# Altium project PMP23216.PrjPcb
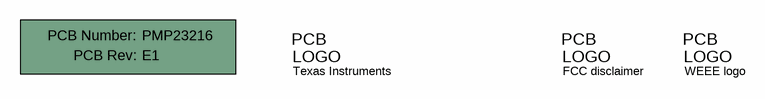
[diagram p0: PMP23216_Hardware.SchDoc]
CopyrightYear: 2022; PCB_Layout: John Gomez; PCB_Rev: E1; PRJ_Customer: Texas Instruments; PRJ_Engineer: John Gomez; PRJ_Number: PMP23216; PRJ_Title: Isolated Bias Supply for PMP22650 with Reinforced Insulation; SCH_Rev: E1; TechSupport: http://www.ti.com/support; TID: N/A
2 sheets, 29 parts. Net scope: global (net labels, ports and power ports of the same name join across sheets).
Board file: PMP23216.PcbDoc
Sheets:
  PMP23216_Hardware.SchDoc
  PMP23216_sheet1.SchDoc

## Sheet PMP23216_Hardware.SchDoc
size 431 x 279 mm; Date: Not shown in title block; ApprovedBy: Not shown in title block; CheckedBy: Not shown in title block; Author: Not shown in title block; CompanyName: Not shown in title block; Engineer: Not shown in title block; Organization: Not shown in title block; Address1: Not shown in title block; Address2: Not shown in title block; Address3: Not shown in title block; Address4: Not shown in title block; DocumentNumber: 1; Revision: Use project parameter SCH_Rev; SheetNumber: 1; SheetTotal: 2; PageSetup: Record=PageOptions¦CenterHorizontal=True¦CenterVertical=True¦PrintScale=1.00¦XCorrection=1.00¦YCorrection=1.00¦PrintKind=0¦BorderSize=5000000¦LeftOffset=0¦BottomOffset=0¦Orientation=2¦PaperLength=1000¦PaperWidth=1000¦Scale=100¦PaperSource=15¦PrintQuality=600¦MediaType=1¦DitherType=10¦PaperKind=Letter¦PrintScaleMode=1

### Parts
!PCB1  Printed Circuit Board  (value not drawn)  (mechanical)
Logo1  Texas Instruments  [TI_Symbol_Overlay_Small]  (no BOM)
Logo2  FCC disclaimer  [FCC_disclaimer]  (no BOM)
Logo3  WEEE logo  [WEEE_Minimum]  (no BOM)

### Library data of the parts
!PCB1 = CMP-0003618-2: Manufacturer: Any; PartNumber: PMP23216
Logo1 = CMP-0074838-1: Texas Instrument Corporate Signature; SymbolCreator: a0412235; Lib Reference: TI_Logo; Library Reference: Logo
Logo2 = CMP-0074847-1: FCC_disclaimer; Library Reference: Logo
Logo3 = CMP-0074769-1

## Sheet PMP23216_sheet1.SchDoc
size A2; DocumentNumber: 2; SheetNumber: 2; SheetTotal: 2; PageSetup: Record=PageOptions¦CenterHorizontal=True¦CenterVertical=True¦PrintScale=0.69¦XCorrection=1.00¦YCorrection=1.00¦PrintKind=0¦BorderSize=5000000¦LeftOffset=0¦BottomOffset=0¦Orientation=2¦PaperLength=1000¦PaperWidth=1000¦Scale=100¦PaperSource=15¦PrintQuality=600¦MediaType=1¦DitherType=10¦PaperKind=Letter¦PrintScaleMode=1
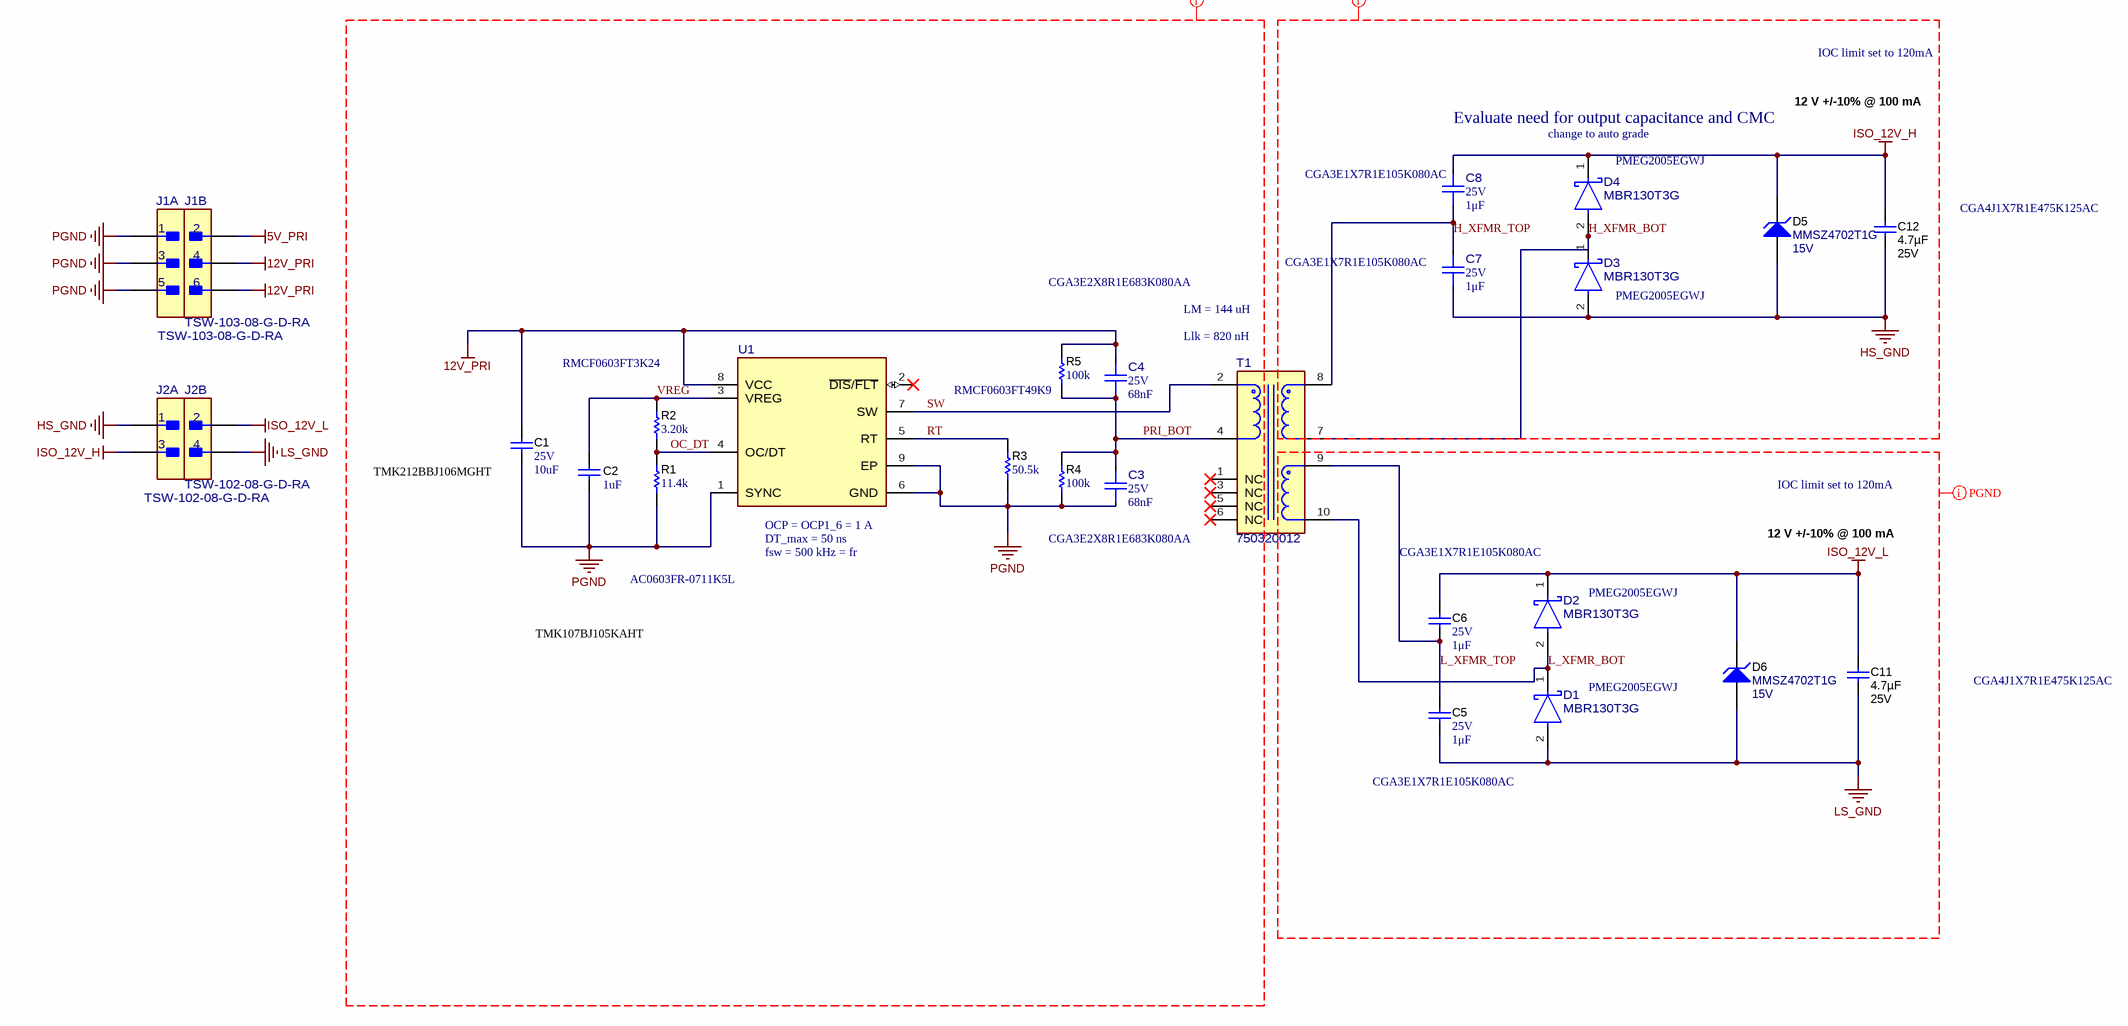
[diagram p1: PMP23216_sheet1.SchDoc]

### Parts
C1  VDC_V: 25V  ValueDisplayed: 10uF  [0805_HV]  (hidden comment: GRM219R61E106KA12D)
C2  ValueDisplayed: 1uF  [0603]  (hidden comment: GRM185R61A105KE36D)
C3  VDC_V: 25V  ValueDisplayed: 68nF  [FP-C1608X8R1E683M080AA_0603-MFG]  (hidden comment: C1608X8R1E683M080AA)
C4  VDC_V: 25V  ValueDisplayed: 68nF  [FP-C1608X8R1E683M080AA_0603-MFG]  (hidden comment: C1608X8R1E683M080AA)
C5  VDC_V: 25V  ValueDisplayed: 1μF  [0603]  (hidden comment: GRM188R61E475KE11D)
C6  VDC_V: 25V  ValueDisplayed: 1μF  [0603]  (hidden comment: GRM188R61E475KE11D)
C7  VDC_V: 25V  ValueDisplayed: 1μF  [FP-C1608X5R1E475M080AC_0603-MFG]  (hidden comment: C1608X5R1E475M080AC)
C8  VDC_V: 25V  ValueDisplayed: 1μF  [FP-C1608X5R1E475M080AC_0603-MFG]  (hidden comment: C1608X5R1E475M080AC)
C11  Cap_F: 4.7µF  VDC_V: 25V  [0805_HV]  (hidden comment: GRM21BR71E475KA73L)
C12  Cap_F: 4.7µF  VDC_V: 25V  [0805_HV]  (hidden comment: GRM21BR71E475KA73L)
D1  MBR130T3G  [FP-MBR130T3G_SOD123-MFG]
D2  MBR130T3G  [FP-MBR130T3G_SOD123-MFG]
D3  MBR130T3G  [FP-MBR130T3G_SOD123-MFG]
D4  MBR130T3G  [FP-MBR130T3G_SOD123-MFG]
D5  MMSZ4702T1G  value 15V  [SOD-123]
D6  MMSZ4702T1G  value 15V  [SOD-123]
J1  TSW-103-08-G-D-RA  [FP-TSW-103-08-G-D-RA_HDR6-MFG]  (parts A,B of 2)
J2  TSW-102-08-G-D-RA  [FP-TSW-102-08-G-D-RA_HDR4-MFG]  (parts A,B of 2)
R1  ValueDisplayed: 11.4k  [0603]  (hidden comment: RT0603DRE0711K4L)
R2  ValueDisplayed: 3.20k  [0603]  (hidden comment: RT0603BRD073K2L)
R3  ValueDisplayed: 50.5k  [0603]  (hidden comment: RT0603DRE0750K5L)
R4  ValueDisplayed: 100k  [0603]  (hidden comment: RT0603BRD073K2L)
R5  ValueDisplayed: 100k  [0603]  (hidden comment: RT0603BRD073K2L)
T1  750320012  [FP-750320012_SMT_XFRMR_20MM48_15MM32-MFG]
U1  UCC25800DGNRQ1  [DGN0008G-MFG]  (value not drawn)

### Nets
5V_PRI: J1.2
12V_PRI: C1.1 C4.2 J1.4 J1.6 R5.2 U1.8(VCC)
HS_GND: C7.1 C12.2 D3.2(ANODE) D5.2(A) J2.1
ISO_12V_H: C8.2 C12.1 D4.1(CATHODE) D5.1(K) J2.3
ISO_12V_L: C6.1 C11.1 D2.1(CATHODE) D6.1(K) J2.2
LS_GND: C5.2 C11.2 D1.2(ANODE) D6.2(A) J2.4
PGND: C1.2 C2.2 C3.1 J1.1 J1.3 J1.5 R1.1 R3.1 R4.1 U1.1(SYNC) U1.6(GND) U1.9(EP)
H_XFMR_BOT: D3.1(CATHODE) D4.2(ANODE) T1.7
H_XFMR_TOP: C7.2 C8.1 T1.8
L_XFMR_BOT: D1.1(CATHODE) D2.2(ANODE) T1.10
L_XFMR_TOP: C5.1 C6.2 T1.9
OC_DT: R1.2 R2.1 U1.4(OC/DT)
PRI_BOT: C3.2 C4.1 R4.2 R5.1 T1.4
RT: R3.2 U1.5(RT)
SW: T1.2 U1.7(SW)
VREG: C2.1 R2.2 U1.3(VREG)

Not connected (* = marked no-connect by the designer): T1 1(NC)* 3(NC)* 5(NC)* 6(NC)*; U1 2(~{DIS}/~{FLT})*

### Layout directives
net class INGND: 12V_PRI, OC_DT, PGND, PRI_BOT, RT, SW, VREG
net class VSWNET: H_XFMR_BOT, H_XFMR_TOP, HS_GND, ISO_12V_H
net class PGND: ISO_12V_L, L_XFMR_BOT, L_XFMR_TOP, LS_GND

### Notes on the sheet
- IOC limit set to 120mA
- Evaluate need for output capacitance and CMC
- 12 V +/-10% @ 100 mA
- (near C8) CGA3E1X7R1E105K080AC
- (near D4) change to auto grade
- (near D4) PMEG2005EGWJ
- CGA4J1X7R1E475K125AC
- CGA3E2X8R1E683K080AA
- LM = 144 uH
- CGA3E1X7R1E105K080AC
- (near D3) PMEG2005EGWJ
- (near R2) RMCF0603FT3K24
- (near R5) RMCF0603FT49K9
- (near T1) Llk = 820 nH
- (near C1) TMK212BBJ106MGHT
- (near U1) OCP = OCP1_6 = 1 A
- AC0603FR-0711K5L
- (near U1) DT_max = 50 ns
- fsw = 500 kHz = fr
- (near D2) PMEG2005EGWJ
- TMK107BJ105KAHT
- (near D1) PMEG2005EGWJ

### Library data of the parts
C1 = CMP-0008206-2: CAP, CERM, 10 uF, 25 V, +/- 10%, X5R, 0805; Manufacturer: MuRata; TaMin_C: -55°C; Polarized: N; SizeAreaWB_mm2: 6.75; Value1: Unknown; U/M: EA; Value: 10uF; TaMax_C: 85°C; SizeZ_mm: 1.45; SizeX_mm: 2; SizeY_mm: 1.25; Cap_Case: 0805; SizeArea_mm2: 2.5; Cap_F: 10µF; AEC Category: Q200
C2 = CMP-0007156-4: CAP, CERM, 1 uF, 10 V, +/- 10%, X5R, 0603; Manufacturer: MuRata; TaMin_C: -55°C; Polarized: N; SizeAreaWB_mm2: 4.68; Value1: Unknown; U/M: EA; Value: 1uF; TaMax_C: 85°C; SizeZ_mm: 1; SizeX_mm: 1.6; SizeY_mm: 0.8; Value2: 10V; SizeArea_mm2: 1.28; Cap_F: 1µF; AEC Category: Q200
C3 C4 = CMP-0094554-1: Multilayer Ceramic Capacitors 68nF ±20% 25V X8R SMD 0603; Manufacturer: TDK; TempCo: 0.15; AEC Qualified: No; Tolerance_%: 0.2%; Voltage: 50V; SizeZ_mm: 0.9mm
C5 C6 = CMP-0007347-4: CAP, CERM, 4.7 uF, 25 V, +/- 10%, X5R, 0603; Manufacturer: MuRata; TaMin_C: -55°C; Polarized: N; SizeAreaWB_mm2: 4.68; Value1: Unknown; U/M: EA; Value: 4.7uF; TaMax_C: 85°C; SizeZ_mm: 1; SizeX_mm: 1.6; SizeY_mm: 0.8; SizeArea_mm2: 1.28; Cap_F: 4.7µF; AEC Category: Q200
C7 C8 = CMP-0094553-1: Multilayer Ceramic Capacitors 4.7μF ±20% 25V X5R SMD 0603; Manufacturer: TDK; Tolerance_%: 0.2%; Voltage: 50V; TempCo: 0.15; SizeZ_mm: 0.9mm; AEC Qualified: No
C11 C12 = CMP-0008346-2: CAP, CERM, 4.7 uF, 25 V, +/- 10%, X7R, 0805; Manufacturer: MuRata; TaMin_C: -55°C; Polarized: N; SizeAreaWB_mm2: 6.75; Value1: Unknown; U/M: EA; Value: 4.7uF; TaMax_C: 125°C; SizeZ_mm: 1.45; SizeX_mm: 2; SizeY_mm: 1.25; Cap_Case: 0805; SizeArea_mm2: 2.5; AEC Category: Q200
D1-D4 = CMP-0094495-1: Diode Schottky 30 V 1A Surface Mount SOD-123; Manufacturer: onsemi; Import Ts: 1521868375; Standoff Height: 0mm; Vr_V: 30V; SizeZ_mm: 1.35mm; Peak Reverse Current: 60uA; TJmax_C: 125°C; Ciiva Ids: 822455; Max Surge Forward Current: 5.5A; AEC Qualified: No
D5 D6 = CMP-0005745-1: Diode, Zener, 15 V, 500 mW, SOD-123; Manufacturer: ON Semiconductor; Power_W: 500mW; SizeAreaWB_mm2: 13.095; Value1: 0.5W; RJA_CperW: 340; U/M: EA; SizeZ_mm: 1.35; SizeX_mm: 3.85; SizeY_mm: 1.7; SizeArea_mm2: 6.545; AEC Category: Q101
J1 = CMP-0090622-1: Connector Header Through Hole, Right Angle 6 position 0.100" (2.54mm); Manufacturer: Samtec; ContactFinish: Gold,Nickel; Current_A: 5.7A; Is Female: no; SizeZ_mm: 5.69mm; Voltage_V: 550V; Row_Count: 2; Conn Gender: Male
J2 = CMP-0088304-1: CONN HEADER R/A 4POS 2.54MM; Manufacturer: Samtec; SizeZ_mm: 5.69mm; Row_Count: 2; ContactFinish: Gold,Tin; AEC Qualified: No; Conn Gender: Male; Conn Orientation: Right Angle
R1 = CMP-0024611-1: RES, 11.4 k, 0.5%, 0.1 W, 0603; Manufacturer: Yageo America; Power_W: 100mW; TempCo: 50 ppm/C; Value_Code: 11k4; U/M: EA; Value: 11.4k; EIA_Code: E192; SizeX_mm: 1.6; SizeY_mm: 0.8; SizeZ_mm: 1; Value2: 0.1W; SizeArea_mm2: 1.28; VDC_V: 75V; AEC Category: Q200
R2 R4 R5 = CMP-0024193-2: RES, 3.20 k, 0.1%, 0.1 W, 0603; Manufacturer: Yageo America; Power_W: 100mW; TempCo: 25 ppm/C; Value_Code: 3k20; U/M: EA; Value: 3.20k; EIA_Code: E192; Res_ohm: 3.2k; SizeX_mm: 1.6; SizeY_mm: 0.8; SizeZ_mm: 1; Value2: 0.1W; SizeArea_mm2: 1.28; VDC_V: 75V; AEC Category: Q200
R3 = CMP-0025375-2: RES, 50.5 k, 0.5%, 0.1 W, 0603; Manufacturer: Yageo America; Power_W: 100mW; TempCo: 50 ppm/C; Value_Code: 50k5; U/M: EA; Value: 50.5k; EIA_Code: E192; SizeX_mm: 1.6; SizeY_mm: 0.8; SizeZ_mm: 1; Value2: 0.1W; SizeArea_mm2: 1.28; VDC_V: 75V; AEC Category: Q200
T1 = CMP-0094840-1: Transformer, 1:1.11:1.11, 0.065Ohm PRI, 0.07Ohm SEC, 141uH, 5000VAC, 20.48x15.32x10.16mm, SMT; Manufacturer: Wurth Electronics; DCR_ohm: 0.065; Rsec1_ohm: 0.07; AEC Qualified: No; Ind_H: 141µH; Voltage_Isolation_Vrms: 5kV
U1 = CMP-0088494-2: Open Loop LLC Transformer Driver for Isolated Bias Supplies; Manufacturer: Texas Instruments; Min Supply Voltage: 12V; SizeZ_mm: 1.1mm; Number Of Outputs: 1; Standoff Height: 0.05mm; AEC Category: Q200; Max Duty Cycle: 50%; TaMin_C: -40°C; TJmax_C: +150°C; AEC Qualified: No; Switching Frequency: 100-2000kHz; CompType: IC; Max Supply Voltage: 36V; TaMax_C: +125°C; Output Type: Other; Nominal Supply Current: 500uA

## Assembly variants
001: not fitted R4 R5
